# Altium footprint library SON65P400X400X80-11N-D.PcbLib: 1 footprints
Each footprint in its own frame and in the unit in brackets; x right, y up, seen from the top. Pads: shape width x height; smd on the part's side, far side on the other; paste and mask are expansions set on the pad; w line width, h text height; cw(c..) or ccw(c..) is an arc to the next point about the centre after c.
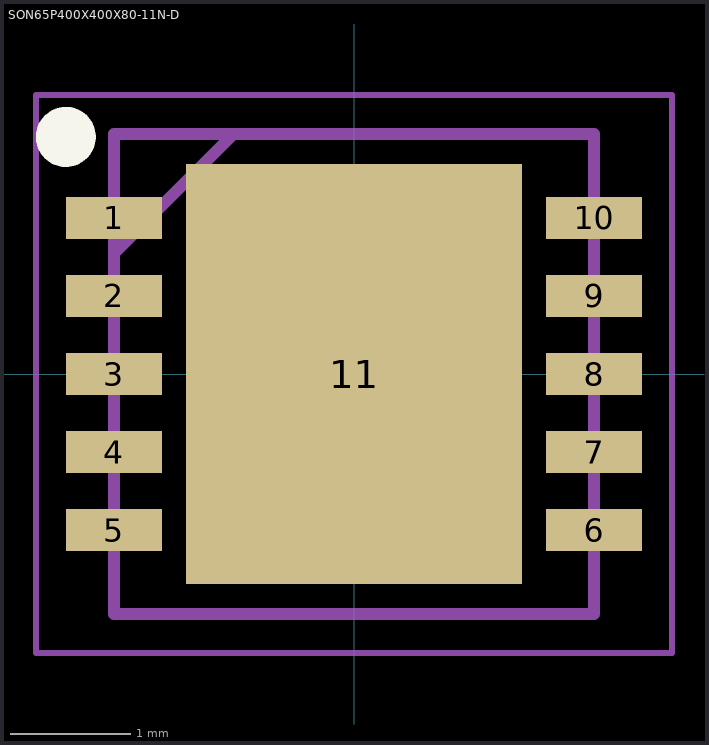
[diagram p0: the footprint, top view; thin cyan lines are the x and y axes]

## SON65P400X400X80-11N-D [mm]
pads (11):
  rect 0.8x0.35 smd: 1(-2,1.3) 2(-2,0.65) 3(-2,0) 4(-2,-0.65) 5(-2,-1.3) 6(2,-1.3) 7(2,-0.65) 8(2,0) 9(2,0.65) 10(2,1.3)
  rect 2.8x3.5 smd: 11(0,0)
Top Overlay:
  circle w0.25: c-2.4,1.975 r0.125
Mechanical 15:
  lines w0.1: -2,1 -1,2 ; -2,-2 2,-2 2,2 -2,2 -2,-2
Mechanical 20:
  lines w0.05: -2.65,-2.325 2.65,-2.325 2.65,2.325 -2.65,2.325 -2.65,-2.325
